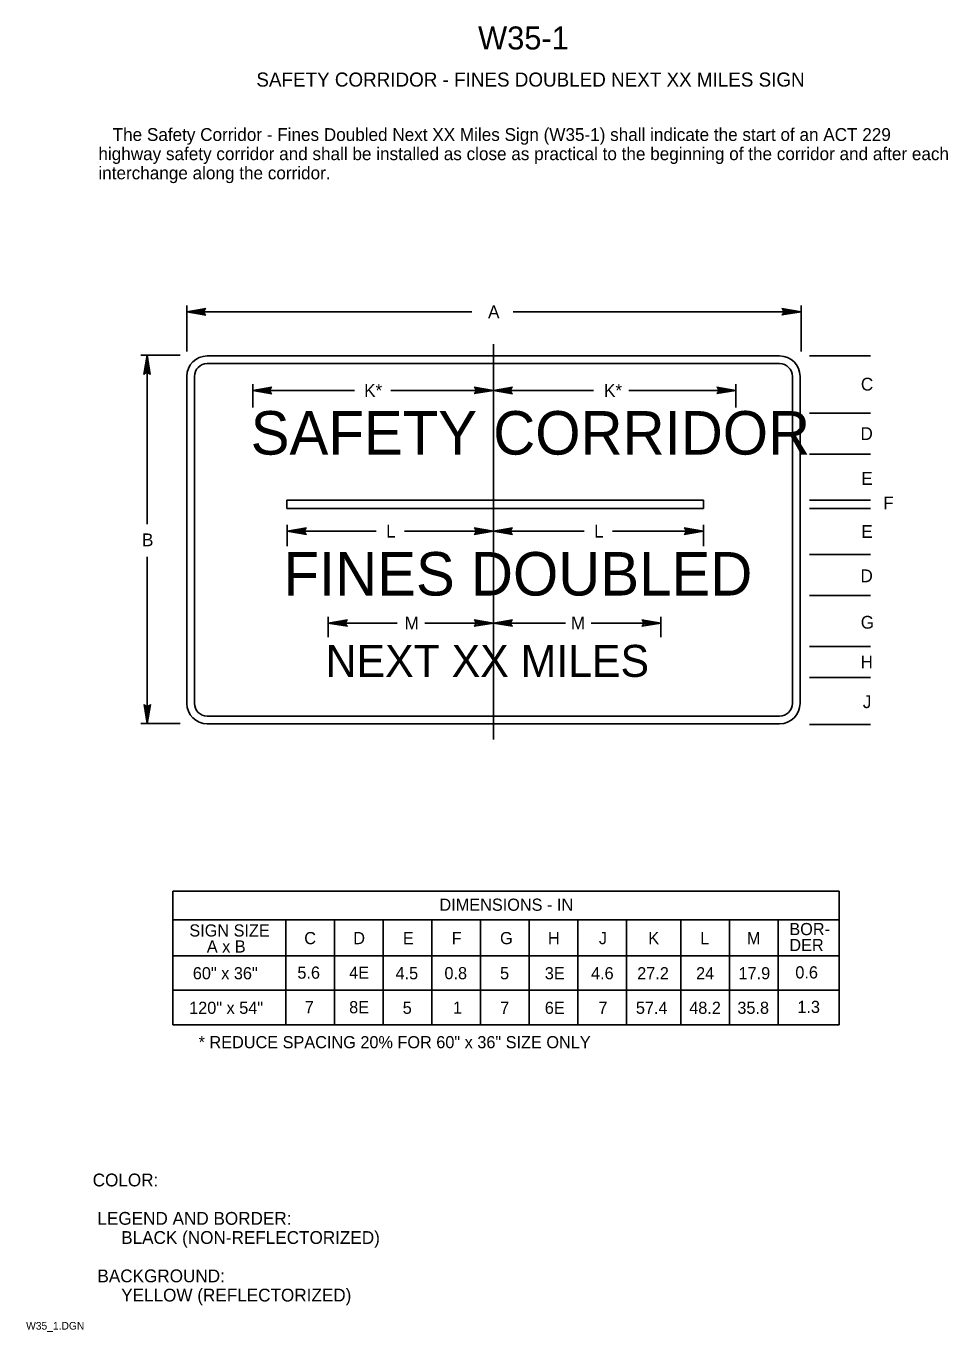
# Model space of a CAD drawing. Extents: x 0.012 to 0.192, y 0.004 to 0.259.
import ezdxf

# ---------------------------------------------------------------- set-up
doc = ezdxf.new("R2010")
doc.units = 0
for name, color, linetype in [('1', 7, 'Continuous'), ('2', 7, 'Continuous'), ('3', 7, 'Continuous')]:
    doc.layers.add(name, color=color, linetype=linetype)

# ---------------------------------------------------------------- blocks, each defined once
blk = doc.blocks.new('RARROW')
at = {"layer": '3'}
for p, q in [((-2.156, 0.285), (-2.2665, 0.384625)), ((-2.2665, 0.384625), (0, 0)), ((0, 0), (-2.2665, -0.379125)), ((-2.156, 0.285), (-2.075625, 0.12075)), ((0, 0), (-2.156, 0.285)), ((-2.14975, -0.2705), (0, 0)), ((-2.075625, 0.12075), (0, 0)), ((0, 0), (-2.074, -0.108)), ((-2.2665, -0.379125), (-2.14975, -0.2705)), ((-2.074, -0.108), (-2.14975, -0.2705))]:
    blk.add_line(p, q, dxfattribs=at)

msp = doc.modelspace()

# ---------------------------------------------------------------- linework, layer by layer
at = {"layer": '1'}
msp.add_line((0.10364, 0.1969), (0.10364, 0.1197), dxfattribs=at)
at = {"layer": '3'}
for p, q in [((0.04375, 0.1955), (0.04375, 0.2045)), ((0.16375, 0.1955), (0.16375, 0.2045)), ((0.09942, 0.20325), (0.04375, 0.20325)), ((0.10749, 0.20325), (0.16375, 0.20325)), ((0.0425, 0.19478), (0.03477, 0.19478)), ((0.03537, 0.191), (0.036, 0.19475)), ((0.036, 0.19475), (0.03553, 0.19118)), ((0.0358, 0.19132), (0.036, 0.19475)), ((0.036, 0.19475), (0.03618, 0.19132)), ((0.03644, 0.19119), (0.036, 0.19475)), ((0.036, 0.19475), (0.03662, 0.191)), ((0.036, 0.16176), (0.036, 0.19475)), ((0.15953, 0.19462), (0.04775, 0.19462)), ((0.1654, 0.19462), (0.17728, 0.19462)), ((0.15953, 0.19312), (0.04775, 0.19312)), ((0.03553, 0.19118), (0.03537, 0.191)), ((0.03553, 0.19118), (0.0358, 0.19132)), ((0.03618, 0.19132), (0.03644, 0.19119)), ((0.03662, 0.191), (0.03644, 0.19119)), ((0.04375, 0.19062), (0.04375, 0.12675)), ((0.04525, 0.19062), (0.04525, 0.12675)), ((0.05663, 0.18455), (0.05663, 0.18913)), ((0.10364, 0.18499), (0.10364, 0.18913)), ((0.15102, 0.18455), (0.15102, 0.18913)), ((0.16203, 0.12675), (0.16203, 0.19062)), ((0.16353, 0.12675), (0.16353, 0.19062)), ((0.07649, 0.18788), (0.05663, 0.18788)), ((0.08361, 0.18788), (0.10364, 0.18788)), ((0.12318, 0.18788), (0.10364, 0.18788)), ((0.13007, 0.18788), (0.15102, 0.18788)), ((0.1654, 0.18343), (0.17728, 0.18343)), ((0.1654, 0.17543), (0.17728, 0.17543)), ((0.06332, 0.16482), (0.06332, 0.16643)), ((0.06332, 0.16643), (0.14466, 0.16643)), ((0.14466, 0.16643), (0.14466, 0.16482)), ((0.1654, 0.16643), (0.17728, 0.16643)), ((0.14466, 0.16482), (0.06332, 0.16482)), ((0.1654, 0.16482), (0.17728, 0.16482)), ((0.06339, 0.15749), (0.06339, 0.16164)), ((0.10364, 0.15864), (0.10364, 0.16164)), ((0.14466, 0.15749), (0.14466, 0.16164)), ((0.08075, 0.16039), (0.06339, 0.16039)), ((0.08627, 0.16039), (0.10364, 0.16039)), ((0.1214, 0.16039), (0.10364, 0.16039)), ((0.12691, 0.16039), (0.14466, 0.16039)), ((0.1654, 0.15583), (0.17728, 0.15583)), ((0.03604, 0.15539), (0.03604, 0.12278)), ((0.1654, 0.14783), (0.17728, 0.14783)), ((0.07138, 0.13965), (0.07138, 0.14368)), ((0.10364, 0.14068), (0.10364, 0.14368)), ((0.13637, 0.13965), (0.13637, 0.14368)), ((0.08488, 0.14243), (0.07138, 0.14243)), ((0.09026, 0.14243), (0.10364, 0.14243)), ((0.11774, 0.14243), (0.10364, 0.14243)), ((0.12272, 0.14243), (0.13637, 0.14243)), ((0.1654, 0.13783), (0.17728, 0.13783)), ((0.1654, 0.13183), (0.17728, 0.13183)), ((0.0425, 0.12278), (0.03477, 0.12278)), ((0.04775, 0.12425), (0.15953, 0.12425)), ((0.04775, 0.12275), (0.15953, 0.12275)), ((0.1654, 0.12263), (0.17728, 0.12263)), ((0.04101, 0.09006), (0.04101, 0.06393)), ((0.04101, 0.09006), (0.17114, 0.09006)), ((0.17114, 0.09006), (0.17114, 0.06393)), ((0.17114, 0.08443), (0.04101, 0.08443)), ((0.06313, 0.08443), (0.06313, 0.06393)), ((0.07263, 0.08443), (0.07263, 0.06393)), ((0.08213, 0.08443), (0.08213, 0.06393)), ((0.09163, 0.08443), (0.09163, 0.06393)), ((0.10113, 0.08443), (0.10113, 0.06393)), ((0.11063, 0.08443), (0.11063, 0.06393)), ((0.12013, 0.08443), (0.12013, 0.06393)), ((0.12963, 0.08443), (0.12963, 0.06393)), ((0.14023, 0.08443), (0.14023, 0.06393)), ((0.14973, 0.08443), (0.14973, 0.06393)), ((0.15923, 0.08443), (0.15923, 0.06393)), ((0.04101, 0.07743), (0.17114, 0.07743)), ((0.04101, 0.07068), (0.17114, 0.07068)), ((0.04101, 0.06393), (0.17114, 0.06393))]:
    msp.add_line(p, q, dxfattribs=at)
for centre, radius, start, end in [((0.04775, 0.19062), 0.004, 90, 180), ((0.15953, 0.19062), 0.004, 0, 90), ((0.04775, 0.19062), 0.0025, 90, 180), ((0.15953, 0.19062), 0.0025, 0, 90), ((0.04775, 0.12675), 0.004, 180, 270), ((0.04775, 0.12675), 0.0025, 180, 270), ((0.15953, 0.12675), 0.004, 270, 0), ((0.15953, 0.12675), 0.0025, 270, 0)]:
    msp.add_arc(centre, radius, start, end, dxfattribs=at)

# ---------------------------------------------------------------- block references
at = {"layer": '3', "xscale": 0.0016545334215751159, "yscale": 0.0016366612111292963}
for p, rotation in [((0.04375, 0.20325), 180), ((0.05663, 0.18788), 180), ((0.10364, 0.18788), 180), ((0.06339, 0.16039), 180), ((0.10364, 0.16039), 180), ((0.07138, 0.14243), 180), ((0.10364, 0.14243), 180), ((0.03604, 0.12278), -90)]:
    msp.add_blockref('RARROW', p, dxfattribs=dict(at, rotation=rotation))
for p in [(0.16375, 0.20325), (0.10364, 0.18788), (0.15102, 0.18788), (0.10364, 0.16039), (0.14466, 0.16039), (0.10364, 0.14243), (0.13637, 0.14243)]:
    msp.add_blockref('RARROW', p, dxfattribs=at)

# ---------------------------------------------------------------- texts
at = {"layer": '1'}
for s, height, p in [('W35-1', 0.0045, (0.10065, 0.2545)), ('SAFETY CORRIDOR - FINES DOUBLED NEXT XX MILES SIGN', 0.0027503, (0.05735, 0.24725)), ('COLOR:', 0.0025, (0.02538, 0.03237)), (' LEGEND AND BORDER:', 0.0024998, (0.02538, 0.02487)), ('      BLACK (NON-REFLECTORIZED)', 0.0024998, (0.02538, 0.02113)), (' BACKGROUND:', 0.0024998, (0.02538, 0.01363)), ('      YELLOW (REFLECTORIZED)', 0.0024998, (0.02538, 0.00988)), ('W35_1.DGN', 0.0015, (0.01238, 0.00438))]:
    msp.add_text(s, height=height, dxfattribs=at).set_placement(p)
at = {"layer": '2'}
for s, height, p in [('   The Safety Corridor - Fines Doubled Next XX Miles Sign (W35-1) shall indicate the start of an ACT 229', 0.00249975, (0.0265, 0.23663)), ('highway safety corridor and shall be installed as close as practical to the beginning of the corridor and after each', 0.00249975, (0.0265, 0.23288)), ('interchange along the corridor.', 0.0024998, (0.0265, 0.22913))]:
    msp.add_text(s, height=height, dxfattribs=at).set_placement(p)
at = {"layer": '3'}
for s, height, p in [('A', 0.0025, (0.1026, 0.202)), ('K*', 0.0025, (0.07839, 0.18663)), ('K*', 0.0025, (0.12524, 0.18663)), ('C', 0.0025, (0.17541, 0.18786)), ('SAFETY CORRIDOR', 0.0085, (0.05624, 0.17535)), ('D', 0.0025, (0.17533, 0.1782)), ('E', 0.0025, (0.17547, 0.16944)), ('F', 0.0025, (0.17978, 0.16466)), ('L', 0.0025, (0.08269, 0.15914)), ('L', 0.0025, (0.12332, 0.15914)), ('E', 0.0025, (0.17547, 0.15907)), ('B', 0.0025, (0.03502, 0.15744)), ('FINES DOUBLED', 0.0085, (0.06263, 0.14781)), ('D', 0.0025, (0.17533, 0.15041)), ('M', 0.0025, (0.0863, 0.14118)), ('M', 0.0025, (0.11879, 0.14118)), ('G', 0.0025, (0.17538, 0.14134)), ('NEXT XX MILES', 0.00625, (0.07088, 0.13192)), ('H', 0.0025, (0.17534, 0.13358)), ('J', 0.0025, (0.17579, 0.12581)), ('DIMENSIONS - IN', 0.0023752, (0.09311, 0.08622)), ('SIGN SIZE', 0.002375, (0.04426, 0.08119)), ('C', 0.00238, (0.0667, 0.07969)), ('D', 0.00238, (0.07627, 0.07969)), ('E', 0.00238, (0.08598, 0.07969)), ('F', 0.00238, (0.09549, 0.07969)), ('G', 0.00238, (0.10494, 0.07969)), ('H', 0.00238, (0.1143, 0.07969)), ('J', 0.00238, (0.12424, 0.07969)), ('K', 0.00238, (0.13389, 0.07969)), ('L', 0.00238, (0.14405, 0.07969)), ('M', 0.00238, (0.15315, 0.07969)), ('BOR-', 0.002375, (0.16144, 0.08146)), ('A x B', 0.002375, (0.04767, 0.07806)), ('DER', 0.002375, (0.16144, 0.07834)), ('60" x 36"', 0.002375, (0.04494, 0.07283)), ('5.6', 0.002375, (0.06536, 0.07295)), ('4E', 0.002375, (0.07547, 0.07295)), ('4.5', 0.002375, (0.08453, 0.07283)), ('0.8', 0.002375, (0.09408, 0.07285)), ('5', 0.00238, (0.10494, 0.07283)), ('3E', 0.002375, (0.11368, 0.07283)), ('4.6', 0.002375, (0.12271, 0.07283)), ('27.2', 0.002375, (0.13173, 0.07283)), ('24', 0.002375, (0.14323, 0.07283)), ('17.9', 0.002375, (0.15152, 0.07283)), ('0.6', 0.002375, (0.16261, 0.073)), ('120" x 54"', 0.002375, (0.04422, 0.06608)), ('7', 0.00238, (0.0668, 0.0662)), ('8E', 0.002375, (0.07547, 0.0662)), ('5', 0.00238, (0.08593, 0.06608)), ('1', 0.00238, (0.09574, 0.0661)), ('7', 0.00238, (0.10497, 0.06608)), ('6E', 0.002375, (0.11368, 0.06608)), ('7', 0.00238, (0.12415, 0.06608)), ('57.4', 0.002375, (0.13147, 0.06608)), ('48.2', 0.002375, (0.14189, 0.06608)), ('35.8', 0.002375, (0.15129, 0.06608)), ('1.3', 0.002375, (0.16301, 0.06625)), ('* REDUCE SPACING 20% FOR 60" x 36" SIZE ONLY', 0.0023752, (0.04607, 0.05936))]:
    msp.add_text(s, height=height, dxfattribs=at).set_placement(p)

doc.saveas('drawing.dxf')
